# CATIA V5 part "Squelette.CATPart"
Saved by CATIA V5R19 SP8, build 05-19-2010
Part number: Squelette
Publications: "Origine", "verticale", "ptsol", "sol", "pt_canonvertical", "axe_canon", "Point_roue", "axe_roue", "Droite_plan_de_construction_verin", "Point_verin_droit", "Point_verin_gauche", "Plan_verin_droit", "Plan_verin_gauche", "Plan_rayon_ext_verin_droit", "Plan_rayon_int_verin_droit", "Plan_rayon_int_verin_gauche", "Plan_rayon_ext_verin_gauche", "Plan_berceaumax", "Plan.9", "Plan.10", "arret_berceau_droit", "arret_berceau_gauche", "arret_berceau_ext_gauche", "arret_berceau_ext_droit", "Droite.8", "Plan.20", "Point.15"
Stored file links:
  G:\EU_thinkMotion\CFAO_2010\MMS_groupe2\MMS_groupe2\OK\mmartini\mmartiniCFAO\Squelette.CATPart
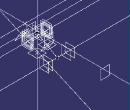
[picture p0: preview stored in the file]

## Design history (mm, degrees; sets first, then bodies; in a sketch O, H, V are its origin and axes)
Parameters
  Hauteur_sol = 1300 mm
  `centre cannon` = 150 mm
  distance_roue_origine = 2500 mm
  rayon_roue = 450 mm
  diametre_canon = 150 mm
  diametre_verin = 120 mm {= diametre_canon *12/15}
AxisSystem1: origin (0, 0, 0), X (1, 0, 0), Y (0, 1, 0), Z (0, 0, 1)
Point1: type OnPlane, Support Plane2, H -450 {= -3*diametre_canon}, V 0, Direction (0, 1, 0)
Set1
  Point2 "Origine": (0, 0, 0), in AxisSystem1
  Line1 "verticale": type Normal, RefPoint Point2, RefSkin xy-plane, Start 0, End 20
  Point3 "ptsol": type OnCurve, Support Line1, Length -1300 {= -8.6666667*diametre_canon}
  Plane1 "sol": type Normal, Curve Line1, RefPoint Point3
  Point4 "pt_canonvertical": type OnCurve, Support Line1, Length 150 {= diametre_canon}
  Line2 "axe_canon": type PtDir, RefPoint Point4, Direction edge [YZ plane of AxisSystem1 | XY plane of AxisSystem1], Start 0, End 20
  Point5 "Point_roue": type OnPlane, Support yz-plane, RefPoint Point3, H 1500 {= diametre_canon *10}, V 450 {= diametre_canon *3}, Direction (0, 1, 0)
  Line3 "axe_roue": type PtDir, RefPoint Point5, Direction edge [XY plane of AxisSystem1 | ZX plane of AxisSystem1], Start 0, End 20
  Line4 "Droite_plan_de_construction_verin": type PtDir, RefPoint Point10, Direction edge [XY plane of AxisSystem1 | ZX plane of AxisSystem1], Start 0, End 20
  Point6 "Point_verin_droit": type OnCurve, Support Line4, Length 675 {= diametre_canon *4.5}
  Point7 "Point_verin_gauche": type OnCurve, Support Line4, Length -675 {= -diametre_canon *4.5}
  Plane2 "Plan_verin_droit": type Normal, Curve Line4, RefPoint Point6
  Plane3 "Plan_verin_gauche": type Normal, Curve Line4, RefPoint Point7
  Plane4 "Plan_rayon_ext_verin_droit": type Offset, RefPlane Plane2, Offset 60 {= diametre_verin /2}
  Plane5 "Plan_rayon_int_verin_droit": type Offset, RefPlane Plane2, Offset -60 {= -diametre_verin /2}
  Plane6 "Plan_rayon_int_verin_gauche": type Offset, RefPlane Plane3, Offset 60 {= diametre_verin /2}
  Plane7 "Plan_rayon_ext_verin_gauche": type Offset, RefPlane Plane3, Offset -60 {= -diametre_verin /2}
  Plane8 "Plan_berceaumax": type Offset, RefPlane zx-plane, Offset 900 {= diametre_canon *6}
  Plane9 "fin_canon": type Offset, RefPlane ZX plane of AxisSystem1, Offset -450 {= -diametre_canon *3}
  Plane10 "Plan_fin_canon": type Offset, RefPlane zx-plane, Offset 5100 {= diametre_canon *34}
  Line5 "axe_berceau_jambe_roue": type PtDir, RefPoint Point1, Direction edge [XY plane of AxisSystem1 | ZX plane of AxisSystem1], Start 0, End 20
  Point8: type OnCurve, Support Line2, Length -900 {= -diametre_canon *6}
  Line6 "axe_berceau_jambe": type PtDir, RefPoint Point8, Direction Line5, Start 0, End 20
  Point9 "point_axe_pivot_canon_berceau": (0, 450 {= diametre_canon *3}, 0), relative to Point2, in AxisSystem1
  Plane11 "arret_berceau_gauche": type Offset, RefPlane yz-plane, Offset -600 {= -diametre_canon *4}
  Plane12 "arret_berceau_droit": type Offset, RefPlane yz-plane, Offset 600 {= diametre_canon *4}
  Plane13 "arret_berceau_ext_gauche": type Offset, RefPlane Plane11, Offset -150 {= -diametre_canon}
  Plane14 "arret_berceau_ext_droit": type Offset, RefPlane Plane12, Offset 150 {= diametre_canon}
  Point10: type OnCurve, Support Line1, Length -200 {= -diametre_canon *1.3333333}
  Point11: type OnCurve, Support Line3, Length 675 {= diametre_canon *4.5}
  Plane15: type Normal, Curve Line3, RefPoint Point11
  Line7: type PtPt, FirstPoint Point1, SecondPoint Point6
  Plane16 "Plan_jambe_gauche_roue": type Offset, RefPlane Plane3, Offset 150 {= diametre_canon}, reversed
  Plane17 "Plan_jambe_droite_roue": type Offset, RefPlane Plane2, Offset 150 {= diametre_canon}
  Point12: type OnCurve, Support Line3, Length -675 {= -diametre_canon *4.5}
  Plane18: type Normal, Curve Line3, RefPoint Point12
  Plane19: type Offset, RefPlane Plane15, Offset 300 {= diametre_canon *2}
  Plane20: type Offset, RefPlane Plane18, Offset 300 {= diametre_canon *2}, reversed
  Line8: type PtPt, FirstPoint Point5, SecondPoint Point2
  Point13: type OnCurve, Support Line8, RefPoint Point2, Length -900 {= -diametre_canon *6}
  Plane21: type Normal, Curve Line8, RefPoint Point13
  Line9: type PtDir, RefPoint Point13, Direction Line1, Start 0, End 20
  Point14: type OnCurve, Support Line9, RefPoint Point13, Length 75 {= diametre_canon /2}
  Plane22: type Normal, Curve Line9, RefPoint Point14
  Plane23: type OffsetPt, RefPlane Plane21, RefPoint Point1
  Point15: type OnPlane, Support Plane23, RefPoint Point1, H 0, V 150 {= diametre_canon}, Direction (1, 0, 0)
  Point16: type OnPlane, Support Plane15, RefPoint Point11, H 0, V -450 {= -diametre_canon *3}, Direction (0, 1, 0)
Body1 (main body)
